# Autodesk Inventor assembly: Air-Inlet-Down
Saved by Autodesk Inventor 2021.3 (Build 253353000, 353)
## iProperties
Created: 2023-07
Part Number: Air-Inlet-Down
Document SubType Name: Assembly
Designer: AdminForWorker
Title: Air-Inlet-Down v2
Author: AdminForWorker
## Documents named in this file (2)
- c:\worker\convert-fusion-r03-cosv3\tmp\job-1\138\output\files\91c07b8a-9802-4b8c-8f6d-c155b046fd28\b978c085-0cdf-47cf-8870-1c04bfdedd3e.iam
- c:\worker\convert-fusion-r03-cosv3\tmp\job-1\138\output\files\91c07b8a-9802-4b8c-8f6d-c155b046fd28\Gland-Replace v10.ipt
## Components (1 placed, 1 different names)
1. Gland-Replace v10:1
